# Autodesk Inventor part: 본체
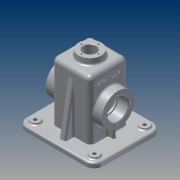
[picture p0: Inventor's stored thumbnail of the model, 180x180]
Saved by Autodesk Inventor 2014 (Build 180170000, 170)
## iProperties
Created: 2015-12
Part Number: 본체
Material: 알루미늄 6061
Document SubType Name: Modeling
Designer: Administrator
Density: 2.71 g/cm^3
Appearance: 알루미늄 - 평지
Mass: 799.892 g
Surface Area: 917.498 cm^2
Volume: 295.163 cm^3
Author: Administrator
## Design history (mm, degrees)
sketch "스케치1"
  geometry: L1 (-50, 57.5)-(50, 57.5); L2 (65, 42.5)-(65, -42.5); L3 (50, -57.5)-(-50, -57.5); L4 (-65, -42.5)-(-65, 42.5); A1 r 15 centre (-50, 42.5) between (-50, 57.5) and (-65, 42.5); A2 r 15 centre (50, 42.5) between (65, 42.5) and (50, 57.5); A3 r 15 centre (50, -42.5) between (50, -57.5) and (65, -42.5); A4 r 15 centre (-50, -42.5) between (-65, -42.5) and (-50, -57.5); 6 further points
  constraints: 8 end point, 8 point on circle, 8 tangent, 6 point on line, 4 centre point, 3 equal radius, 2 midpoint, 2 parallel, 1 horizontal, 1 horizontal alignment, 1 perpendicular, 1 vertical alignment
  dimensions: "d0" = 130 distance of point (-65, 57.5) point (65, 57.5); "d1" = 115 distance of point (65, 57.5) point (65, -57.5); "d2" = 15 radius of A1
extrude "돌출1" new body sketch "스케치1" distance "d3" = 10; taper "d4" = 0 deg
sketch "스케치2"
  geometry: L1 (-32.5, 32.5)-(32.5, 32.5); L2 (32.5, 32.5)-(32.5, -32.5); L3 (32.5, -32.5)-(-32.5, -32.5); L4 (-32.5, -32.5)-(-32.5, 32.5); 3 further points
  constraints: 8 end point, 2 midpoint, 2 parallel, 1 horizontal, 1 horizontal alignment, 1 perpendicular, 1 vertical alignment
  dimensions: "d5" = 65 distance of L1.end L2.end; "d6" = 65 distance of L1.start L1.end
extrude "돌출2" join sketch "스케치2" distance "d7" = 100; taper "d8" = 0 deg
sketch "스케치6"
  geometry: C1 r 27.5 at (-45, 32.5); 1 further point
  constraints: 1 centre point
  dimensions: "d17" = 55 distance of point (10, 32.5) C1.centre; "d18" = 55 diameter of C1
extrude "돌출3" join sketch "스케치6" distance "d19" = 15; taper "d20" = 0 deg
hole "구멍1" diameter "d23" = 30; stored, may be unused: countersink angle "d27" = 90 deg, drill point angle "d29" = 118 deg; dims "d24" = 6, "d25" = 35, "d26" = 17, "d28" = 8, "d30" = 10, "d31" = 10
sketch "스케치7"
  geometry: C1 r 17.5 at (0, 0) reference; 2 further points
  constraints: 1 horizontal alignment
  dimensions: "d32" = 21 distance of C1.centre point (-21, 0)
hole "구멍2" sketch "스케치7" at (-21, 0) diameter "d33" = 3.242; stored, may be unused: countersink angle "d37" = 90 deg, drill point angle "d39" = 118 deg; dims "d34" = 8, "d35" = 42, "d36" = 17, "d38" = 10
sketch "스케치8"
  geometry: L1 (-27.5, 27.5)-(27.5, 27.5); L2 (27.5, 27.5)-(27.5, -27.5); L3 (27.5, -27.5)-(-27.5, -27.5); L4 (-27.5, -27.5)-(-27.5, 27.5); 3 further points
  constraints: 8 end point, 2 midpoint, 2 parallel, 1 horizontal, 1 horizontal alignment, 1 perpendicular, 1 vertical alignment
  dimensions: "d43" = 55 distance of L1.start L1.end; "d44" = 55 distance of L1.end L2.end
extrude "돌출4" cut sketch "스케치8" distance "d45" = 105; taper "d46" = 0 deg
sketch "스케치9"
  geometry: C1 r 20 at (0, 0); 1 further point
  constraints: 1 centre point, 1 coincident
  dimensions: "d47" = 40 diameter of C1
extrude "돌출5" join sketch "스케치9" distance "d48" = 10; taper "d49" = -5 deg
hole "구멍3" diameter "d52" = 21; stored, may be unused: countersink angle "d56" = 90 deg, drill point angle "d58" = 118 deg; dims "d50" = 10, "d51" = 10, "d53" = 8, "d54" = 42, "d55" = 17, "d57" = 10
sketch "스케치10"
  geometry: C1 r 10.5 at (0, 0) reference; 1 further point
  constraints: 1 horizontal alignment
  dimensions: "d59" = 14.5 distance of point (14.5, 0) C1.centre
hole "구멍4" sketch "스케치10" at (14.5, 0) diameter "d60" = 2.459; stored, may be unused: countersink angle "d64" = 90 deg, drill point angle "d66" = 118 deg; dims "d61" = 7, "d62" = 42, "d63" = 17, "d65" = 9
sketch "스케치11"
  geometry: L1 (50, 57.5)-(-50, 57.5) reference; L2 (-65, 42.5)-(-65, -42.5) reference; L3 (-50, -57.5)-(50, -57.5) reference; L4 (65, -42.5)-(65, 42.5) reference; L5 (-50, 52.5)-(50, 52.5); L6 (60, 42.5)-(60, -42.5); L7 (50, -52.5)-(-50, -52.5); L8 (-60, -42.5)-(-60, 42.5); A1 r 15 centre (-50, 42.5) between (-50, 57.5) and (-65, 42.5) reference; A2 r 15 centre (-50, -42.5) between (-65, -42.5) and (-50, -57.5) reference; A3 r 15 centre (50, -42.5) between (50, -57.5) and (65, -42.5) reference; A4 r 15 centre (50, 42.5) between (65, 42.5) and (50, 57.5) reference; A5 r 10 centre (-50, 42.5) between (-50, 52.5) and (-60, 42.5); A6 r 10 centre (50, 42.5) between (60, 42.5) and (50, 52.5); A7 r 10 centre (50, -42.5) between (50, -52.5) and (60, -42.5); A8 r 10 centre (-50, -42.5) between (-60, -42.5) and (-50, -52.5); 6 further points
  constraints: 8 end point, 8 point on circle, 8 tangent, 6 point on line, 4 centre point, 3 equal radius, 2 midpoint, 2 parallel, 1 horizontal, 1 horizontal alignment, 1 perpendicular, 1 vertical alignment
  dimensions: "d70" = 120 distance of point (-60, 52.5) point (60, 52.5); "d71" = 105 distance of point (60, 52.5) point (60, -52.5); "d72" = 10 radius of A5
extrude "돌출6" cut sketch "스케치11" distance "d73" = 2; taper "d74" = 0 deg
sketch "스케치12"
  geometry: C1 r 7.5 at (-50, 42.5); C2 r 7.5 at (-50, -42.5); C3 r 7.5 at (50, -42.5); C4 r 7.5 at (50, 42.5); A1 r 15 centre (-50, 42.5) between (-50, 57.5) and (-65, 42.5) reference; A2 r 15 centre (-50, -42.5) between (-65, -42.5) and (-50, -57.5) reference; A3 r 15 centre (50, -42.5) between (50, -57.5) and (65, -42.5) reference; A4 r 15 centre (50, 42.5) between (65, 42.5) and (50, 57.5) reference; 1 further point
  constraints: 4 centre point, 4 coincident, 2 equal radius
  dimensions: "d75" = 15 diameter of C1; "d76" = 15 diameter of C2
extrude "돌출7" join sketch "스케치12" distance "d77" = 3; taper "d78" = 0 deg
sketch "스케치13"
  geometry: C1 r 7.5 at (0, 0) reference; C2 r 7.5 at (0, 85) reference; C3 r 7.5 at (-100, 85) reference; C4 r 7.5 at (-100, 0) reference; 5 further points
  constraints: 4 coincident
hole "구멍5" sketch "스케치13" at (-100, 85), (-100, 0), (0, 0), (0, 85) diameter "d79" = 6; stored, may be unused: countersink angle "d83" = 90 deg, drill point angle "d85" = 118 deg; dims "d80" = 7, "d81" = 42, "d82" = 17, "d84" = 9
sketch "스케치14"
  geometry: L1 (32.5, 82.5)-(47.5, 82.5) reference; L2 (47.5, 82.5)-(47.5, 77.621) reference; L3 (47.5, 77.621)-(37.5, 77.621) reference; L4 (37.5, 77.621)-(36.526, 76) reference; L5 (36.526, 76)-(37.5, 74.379) reference; L6 (37.5, 74.379)-(47.5, 74.379) reference; L7 (47.5, 74.379)-(47.5, 72.5) reference; L8 (47.5, 72.5)-(30.5, 72.5) reference; L9 (30.5, 72.5)-(30.5, 70) reference; L10 (30.5, 70)-(27.5, 70) reference; L11 (27.5, 70)-(27.5, 105) reference; L12 (27.5, 105)-(10.5, 105) reference; L13 (10.5, 105)-(10.5, 120) reference; L14 (10.5, 120)-(13.271, 120) reference; L15 (13.271, 120)-(13.271, 111) reference; L16 (13.271, 111)-(14.5, 110.261) reference; L17 (14.5, 110.261)-(15.73, 111) reference; L18 (15.73, 111)-(15.73, 120) reference; L19 (15.73, 120)-(19.125, 120) reference; L20 (19.125, 120)-(20, 110) reference; L21 (20, 110)-(32.5, 110) reference; L22 (32.5, 110)-(32.5, 82.5) reference; L23 (47.5, 27.5)-(32.5, 27.5) reference; L24 (32.5, 27.5)-(32.5, 10) reference; L25 (32.5, 10)-(65, 10) reference; L26 (65, 10)-(65, 2) reference; L27 (65, 2)-(60, 2) reference; L28 (60, 2)-(60, 0) reference; L29 (60, 0)-(27.5, 0) reference; L30 (27.5, 0)-(27.5, 40) reference; L31 (27.5, 40)-(30.5, 40) reference; L32 (30.5, 40)-(30.5, 37.5) reference; L33 (30.5, 37.5)-(47.5, 37.5) reference; L34 (47.5, 37.5)-(47.5, 35.621) reference; L35 (47.5, 35.621)-(37.5, 35.621) reference; L36 (37.5, 35.621)-(36.526, 34) reference; L37 (36.526, 34)-(37.5, 32.379) reference; L38 (37.5, 32.379)-(47.5, 32.379) reference; L39 (47.5, 32.379)-(47.5, 27.5) reference; L40 (-47.5, 82.5)-(-32.5, 82.5) reference; L41 (-32.5, 82.5)-(-32.5, 110) reference; L42 (-32.5, 110)-(-20, 110) reference; L43 (-20, 110)-(-19.125, 120) reference; L44 (-19.125, 120)-(-15.73, 120) reference; L45 (-15.73, 120)-(-15.73, 111) reference; L46 (-15.73, 111)-(-14.5, 110.261) reference; L47 (-14.5, 110.261)-(-13.271, 111) reference; L48 (-13.271, 111)-(-13.271, 120) reference; L49 (-13.271, 120)-(-10.5, 120) reference; L50 (-10.5, 120)-(-10.5, 105) reference; L51 (-10.5, 105)-(-27.5, 105) reference; L52 (-27.5, 105)-(-27.5, 70) reference; L53 (-27.5, 70)-(-30.5, 70) reference; L54 (-30.5, 70)-(-30.5, 72.5) reference; L55 (-30.5, 72.5)-(-47.5, 72.5) reference; L56 (-47.5, 72.5)-(-47.5, 74.379) reference; L57 (-47.5, 74.379)-(-37.5, 74.379) reference; L58 (-37.5, 74.379)-(-36.526, 76) reference; L59 (-36.526, 76)-(-37.5, 77.621) reference; L60 (-37.5, 77.621)-(-47.5, 77.621) reference; L61 (-47.5, 77.621)-(-47.5, 82.5) reference; L62 (-32.5, 27.5)-(-47.5, 27.5) reference; L63 (-47.5, 27.5)-(-47.5, 32.379) reference; L64 (-47.5, 32.379)-(-37.5, 32.379) reference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; 1 further point
  constraints: 16 end point, 4 collinear, 2 point on line, 2 vertical, 1 parallel, 1 perpendicular
  dimensions: "d87" = 15 distance between parallel lines of L72 L79; "d88" = 15 distance between parallel lines of L80 L30; "d89" = 20.28589 distance of L79.start L79.end; "d90" = 20.28651 distance of L80.start L80.end
extrude "돌출8" join sketch "스케치14" stored distance "d91" = 6; taper "d92" = 0 deg
sketch "스케치15"
  geometry: L1 (-32.5, 10)-(-32.5, 110) reference; L2 (-32.5, 110)-(-20, 110) reference; L3 (-20, 110)-(-19.125, 120) reference; L4 (-19.125, 120)-(-15.73, 120) reference; L5 (-15.73, 120)-(-15.73, 111) reference; L6 (-15.73, 111)-(-14.5, 110.261) reference; L7 (-14.5, 110.261)-(-13.271, 111) reference; L8 (-13.271, 111)-(-13.271, 120) reference; L9 (-13.271, 120)-(-10.5, 120) reference; L10 (-10.5, 120)-(-10.5, 105) reference; L11 (-10.5, 105)-(-27.5, 105) reference; L12 (-27.5, 105)-(-27.5, 0) reference; L13 (-27.5, 0)-(-52.5, 0) reference; L14 (-52.5, 0)-(-52.5, 2) reference; L15 (-52.5, 2)-(-57.5, 2) reference; L16 (-57.5, 2)-(-57.5, 10) reference; L17 (-57.5, 10)-(-32.5, 10) reference; L18 (32.5, 110)-(32.5, 10) reference; L19 (32.5, 10)-(57.5, 10) reference; L20 (57.5, 10)-(57.5, 2) reference; L21 (57.5, 2)-(52.5, 2) reference; L22 (52.5, 2)-(52.5, 0) reference; L23 (52.5, 0)-(27.5, 0) reference; L24 (27.5, 0)-(27.5, 105) reference; L25 (27.5, 105)-(10.5, 105) reference; L26 (10.5, 105)-(10.5, 120) reference; L27 (10.5, 120)-(13.271, 120) reference; L28 (13.271, 120)-(13.271, 111) reference; L29 (13.271, 111)-(14.5, 110.261) reference; L30 (14.5, 110.261)-(15.73, 111) reference; L31 (15.73, 111)-(15.73, 120) reference; L32 (15.73, 120)-(19.125, 120) reference; L33 (19.125, 120)-(20, 110) reference; L34 (20, 110)-(32.5, 110) reference; L35 (-32.5, 95.069)-(-47.5, 10); L36 (32.5, 95.069)-(47.5, 10); 1 further point
  constraints: 4 end point, 4 point on line
  dimensions: "d93" = 10 deg angle of L35 L16; "d94" = 10 deg angle of L20 L36; "d95" = 10 distance from line of L35.end L16; "d96" = 10 distance from line of L36.end L20
extrude "돌출9" join sketch "스케치15" stored distance "d97" = 10; taper "d98" = 0 deg
chamfer "모따기1" distance "d99" = 1; stored, may be unused: second distance "d100" = 2, angle "d101" = 45 deg
fillet "모깎기2" dims "d102" = 0.3
fillet "모깎기3" dims "d103" = 8
fillet "모깎기4" dims "d104" = 3
fillet "모깎기5" dims "d105" = 3
fillet "모깎기6" dims "d106" = 3
fillet "모깎기7" dims "d107" = 1
sketch "스케치17"
  geometry: L1 (0, -8)-(91, -8) reference; L2 (-18, 5.375)-(-18, 43.625) reference; 2 further points
  constraints: 1 other
  dimensions: "d112" = 32.5 distance from line of point (8, 24.5) L1; "d113" = 26 distance from line of L2 point (8, 24.5)
feature "엠보싱2" sketch "스케치17" dims "d0" = 130, "d1" = 115, "d2" = 15, "d114" = 0.5, "d115" = 0
node "솔리드1"
pattern_circular "원형 패턴1" dims angle "d41" = 360 deg
mirror "대칭1"
pattern_circular "원형 패턴2" dims angle "d68" = 360 deg
node "절단 모서리 투영1"
node "절단 모서리 투영2"
